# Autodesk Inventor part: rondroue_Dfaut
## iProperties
Created: 2007-07
Part Number: rondroue_Dfaut
Document SubType Name: Modeling
Designer: EF
Density: 1 g/cm^3
Author: EF
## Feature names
1. Base1
